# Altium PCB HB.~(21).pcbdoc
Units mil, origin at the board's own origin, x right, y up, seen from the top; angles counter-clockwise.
Board outline 4000 x 2100 mil, 2 copper layers (Top Layer, Bottom Layer); 61 components, 37 nets, 226 pads, 50 vias.
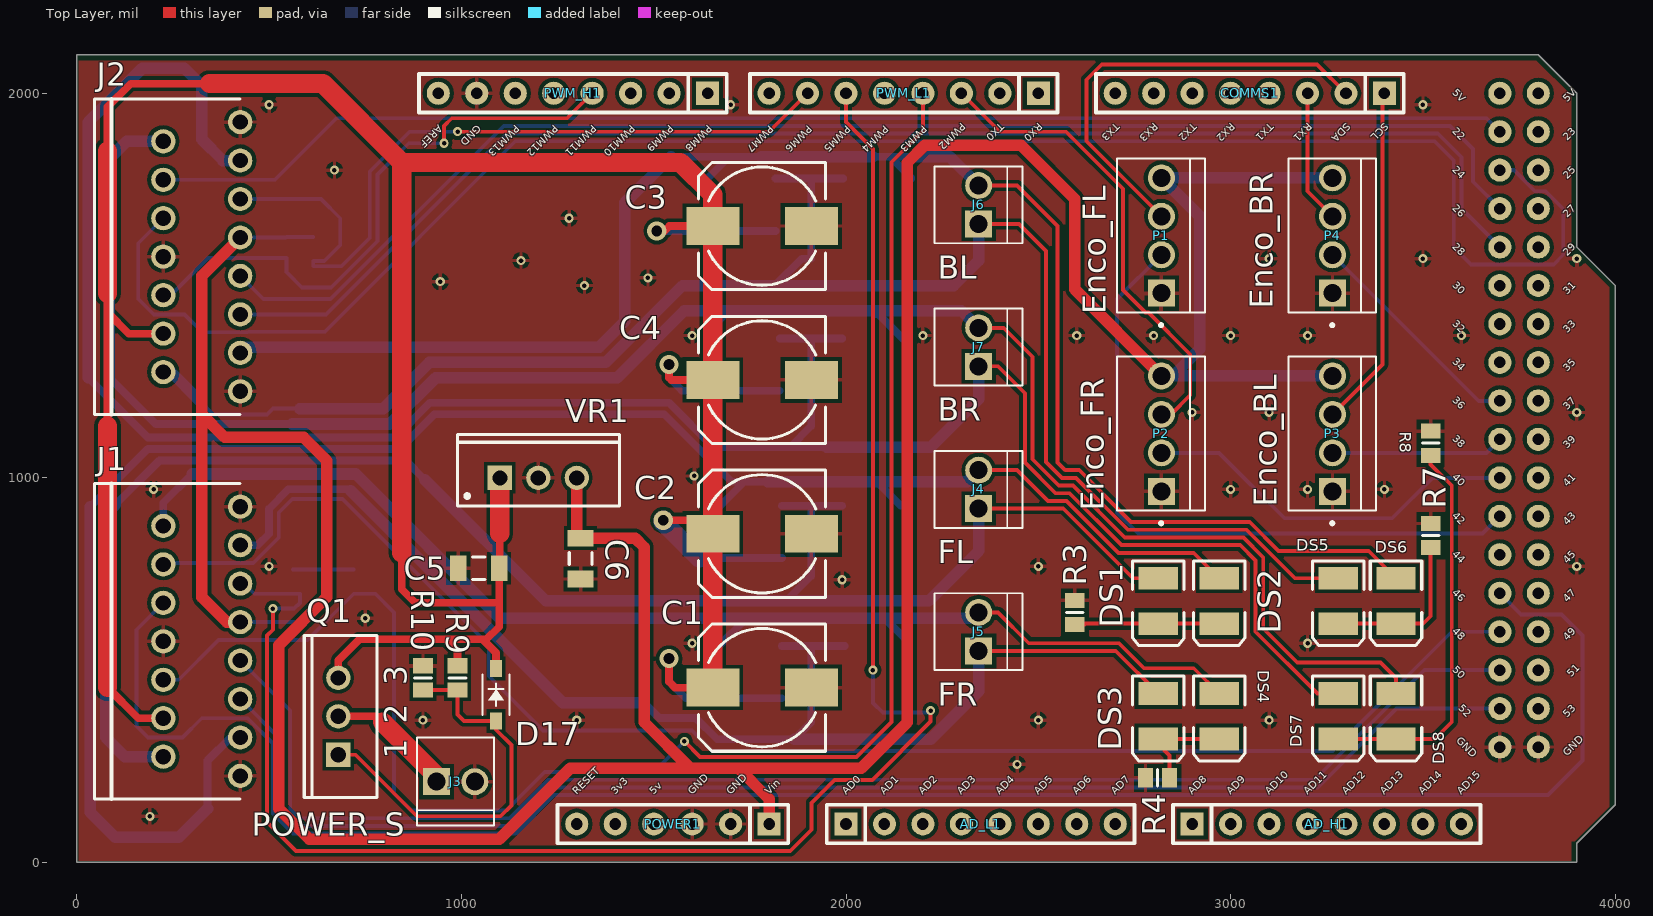
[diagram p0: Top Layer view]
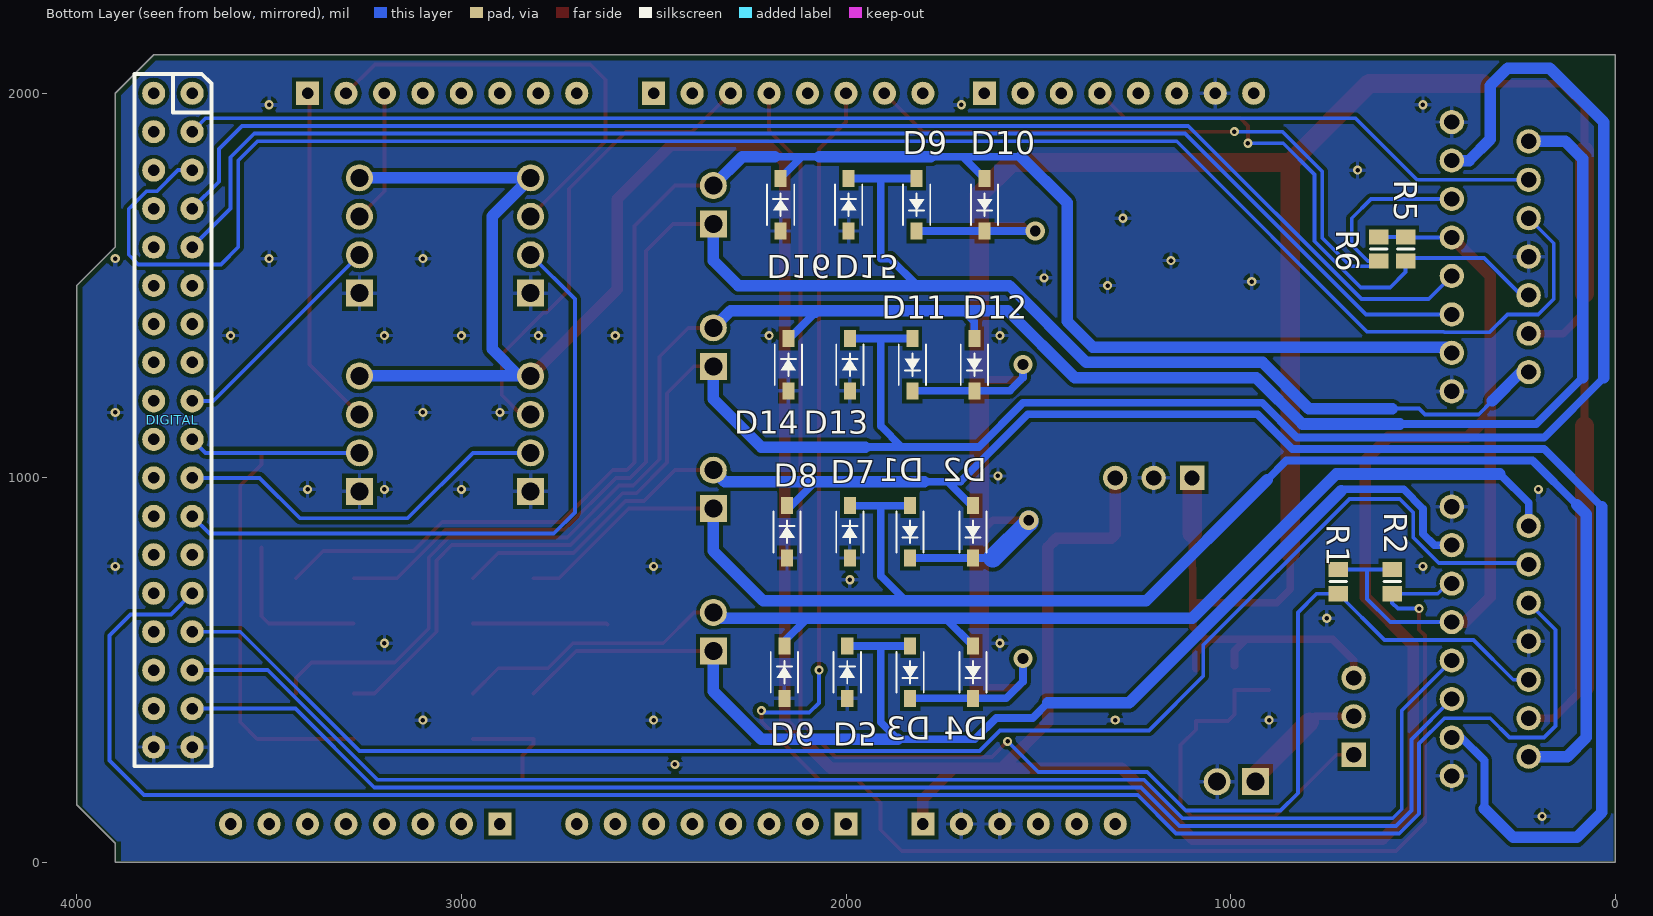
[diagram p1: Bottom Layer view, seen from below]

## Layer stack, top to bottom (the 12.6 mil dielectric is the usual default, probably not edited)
Top Solder: solder mask 0.4, Solder Resist, Dk 3.5
Top Layer: signal copper 1.4
Dielectric1: dielectric 12.6, FR-4, Dk 4.8
Bottom Layer: signal copper 1.4
Bottom Solder: solder mask 0.4, Solder Resist, Dk 3.5

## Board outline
0,0 0,2100 3800,2100 3900,2000 3900,1600 4000,1500 4000,150 3900,50 3900,0

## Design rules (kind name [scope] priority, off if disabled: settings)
Clearance [All] p1: gap=10 ignorepadtopadclearanceinfootprint=FALSE except(0: Arc-Text Track-Text SMDPad-Text THPad-Text Via-Text Fill-Text Poly-Text Region-Text Text-Text)
Clearance POWER [InNet('GND') vs InNet('+12V')] p2: gap=20 ignorepadtopadclearanceinfootprint=FALSE
ComponentClearance [All] p1: gap=7 collisioncheckmode=3 verticalgap=7 showdistances=FALSE
PolygonConnect [All] p1: connectstyle=Relief reliefconductorwidth=10 reliefentries=4 polygonreliefangle="90 Angle" airgapwidth=10
RoutingVias RoutingVias_1 [InNet('+12V')] p1: holewidth=28 width=50 viastyle="Through Hole" minholewidth=28 minwidth=50 maxholewidth=28 maxwidth=50 useviatemplates=TRUE viatemplateguid#1={C0CBB304-7D75-4EF7-981A-080250C0CCCD} viatemplatename#1=v127h71
RoutingVias [All] p2: holewidth=28 width=50 viastyle="Through Hole" minholewidth=28 minwidth=50 maxholewidth=28 maxwidth=50 useviatemplates=TRUE viatemplateguid#1={6204ABBA-D726-4070-AECC-2A288C87648D} viatemplatename#1=v60h30
SilkToSilkClearance [All] p1: silktosilkclearance=5
SilkToSolderMaskClearance SilkscreenOverComponentPads [IsPad] p1: minsilkscreentomaskgap=7 clearancetoexposedcopper=TRUE
SolderMaskExpansion [All] p1: expansion=4
Width motor [InNet('motor_BL1')+InNet('motor_BL2')+InNet('motor_BR1')+InNet('motor_BR2')+InNet('motor_FL1')+InNet('motor_FL2')+InNet('motor_FR1')+InNet('motor_FR2')] p1: maxlimit=30 minlimit=10 preferedwidth=20
Width 12V [InNet('+12V')] p2: maxlimit=50 minlimit=10 preferedwidth=20
Width POWER_route [InNet('VCC')] p3: maxlimit=50 minlimit=15 preferedwidth=20
Width [All] p4: maxlimit=30 minlimit=10 preferedwidth=10
27 further rules are at their usual default settings.

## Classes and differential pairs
component class HB_main: AD_H1 AD_L1 COMMS1 DIGITAL J3 J4 J5 J6 J7 P1 P2 P3 P4 POWER1 PWM_H1 PWM_L1
component class Designator: D9 D10 D11 D12 D13 D14 D15 D16 DS5 DS6 DS7 DS8 J2 R5 R6 R7 R8

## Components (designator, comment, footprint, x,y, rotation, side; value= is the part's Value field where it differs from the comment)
AD_H1 "AD_H" "Header 8x1 8.5mm" 2900,100 r0 top
AD_L1 "AD_L" "Header 8x1 8.5mm" 2000,100 r0 top
C1 "Cap_220u" CAPAE0810X700N 1781.73,454.6 r180 top value=220u
C2 "Cap_220u" CAPAE0810X700N 1781.73,854.6 r180 top value=220u
C3 "Cap_220u" CAPAE0810X700N 1781.73,1654.6 r180 top value=220u
C4 "Cap_220u" CAPAE0810X700N 1781.73,1254.6 r180 top value=220u
C5 "Cap_330n" C1206 1045,765 r180 top value=330n
C6 "Cap_100n" C1206 1310,790 r270 top value=100n
COMMS1 "Communication" "Header 8x1 8.5mm" 3400,2000 r180 top
D1 "Diode Schottky" SOD-123 1833.54,859.53 r90 bottom
D2 "Diode Schottky" SOD-123 1670,859.53 r90 bottom
D3 "Diode Schottky" SOD-123 1833.23,494.76 r90 bottom
D4 "Diode Schottky" SOD-123 1669.69,494.76 r90 bottom
D5 "Diode Schottky" SOD-123 1996.77,494.76 r270 bottom
D6 "Diode Schottky" SOD-123 2160.32,494.76 r270 bottom
D7 "Diode Schottky" SOD-123 1990,859.53 r270 bottom
D8 "Diode Schottky" SOD-123 2153.54,859.53 r270 bottom
D9 "Diode Schottky" SOD-123 1816.46,1710 r90 bottom
D10 "Diode Schottky" SOD-123 1639.68,1710 r90 bottom
D11 "Diode Schottky" SOD-123 1827.48,1294.29 r90 bottom
D12 "Diode Schottky" SOD-123 1666.3,1294.29 r90 bottom
D13 "Diode Schottky" SOD-123 1990,1294.29 r270 bottom
D14 "Diode Schottky" SOD-123 2149.84,1294.29 r270 bottom
D15 "Diode Schottky" SOD-123 1993.23,1710 r270 bottom
D16 "Diode Schottky" SOD-123 2170,1710 r270 bottom
D17 "D Zener" SOD-123 1090,436.1 r270 top
DIGITAL "IO_36" "HEADER 36X 8MM" 3700,2000 r270 bottom
DS1 "LED" 3.5X2.8X1.9 2812.13,680 r270 top
DS2 "LED" 3.5X2.8X1.9 2970,680 r270 top
DS3 "LED" 3.5X2.8X1.9 2812.13,380 r270 top
DS4 "LED" 3.5X2.8X1.9 2970,380 r270 top
DS5 "LED" 3.5X2.8X1.9 3280,680 r270 top
DS6 "LED" 3.5X2.8X1.9 3430,680 r270 top
DS7 "LED" 3.5X2.8X1.9 3280,380 r270 top
DS8 "LED" 3.5X2.8X1.9 3430,380 r270 top
J1 "L298" MultiWatt15 425,65 r90 top
J2 "L298" MultiWatt15 425,1065 r90 top
J3 "POWER_S" Header_2 1085,210.79 r180 top
J4 "FL" Header_2 2344.21,1070 r270 top
J5 "FR" Header_2 2344.21,700 r270 top
J6 "BL" Header_2 2344.21,1810 r270 top
J7 "BR" Header_2 2344.21,1440 r270 top
P1 "Enco_FL" MOLEX_22-27-2081 2819.21,1830 r270 top
P2 "Enco_FR" MOLEX_22-27-2081 2819.21,1315 r270 top
P3 "Enco_BL" MOLEX_22-27-2081 3264.21,1315 r270 top
P4 "Enco_BR" MOLEX_22-27-2081 3264.21,1830 r270 top
POWER1 "POWER" "Header 6x1 8.5mm" 1800,100 r180 top
PWM_H1 "PWM_H" "Header 8x1 8.5mm" 1640,2000 r180 top
PWM_L1 "PWM_L" "Header 8x1 8.5mm" 2500,2000 r180 top
Q1 "MOSFET-P" TO-220-AB 680,380 r90 top
R1 "Res_10k" 6-0805_L 720,730 r270 bottom value=10k
R2 "Res_10k" 6-0805_L 580,730 r90 bottom value=10k
R3 "Res_2.2k" 6-0805_L 2595,650 r270 top value=2.2k
R4 "Res_2.2k" 6-0805_L 2810,220 r0 top value=2.2k
R5 "Res_10k" 6-0805_L 545,1595 r270 bottom value=10k
R6 "Res_10k" 6-0805_L 615,1595 r90 bottom value=10k
R7 "Res_2.2k" 6-0805_L 3520,850 r270 top value=2.2k
R8 "Res_2.2k" 6-0805_L 3520,1090 r270 top value=2.2k
R9 "Res_100k" 6-0805_L 990,480 r90 top value=100k
R10 "Res_1k" 6-0805_L 900,480 r270 top value=1k
VR1 "7805" TO-220AB 1200,1000 r0 top

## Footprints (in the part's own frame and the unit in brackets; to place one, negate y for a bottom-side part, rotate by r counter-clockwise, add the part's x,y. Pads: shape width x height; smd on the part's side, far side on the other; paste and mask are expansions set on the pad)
3.5X2.8X1.9 [mm] "SM LED; 2 C-Bend Leads; Body 3.5 x 2.8 x 1.9 mm, inc leads (LxWxH typ)"
  rect 1.5x2.6 smd: 1(-1.5,0) 2(1.5,0)
  silkscreen extent -2.65,-1.7 2.95,1.7
6-0805_L [mm] "Chip Resistor, Body 2.0x1.2mm, IPC High Density"
  rect 1x1.3 smd: 1(-0.8,0) 2(0.8,0)
  silkscreen extent 0,-0.55 0,0.55, body extent -1.07,-0.7 1.07,0.7, height 0.7
C1206 [mm] "Chip Capacitor, Body 3.2x1.6mm, IPC High Density"
  rect 1.1x1.7 smd: 1(-1.35,0) 2(1.35,0)
  silkscreen extent -0.4,-0.75 0.4,0.75, body extent -1.7,-0.9 1.7,0.9, height 1.3
CAPAE0810X700N [mm]
  rect 3.5x2.5 smd: NEG(-3.25,0) POS(3.25,0)
  silkscreen extent -4.2,-4.2 4.2,4.2
"Header 6x1 8.5mm" [mil] "Stackable 6 pin header"
  rect 60x60 hole 30: 1(0,0)
  round 60 hole 30: 2(100,0) 3(200,0) 4(300,0) 5(400,0) 6(500,0)
  silkscreen extent -50,-50 550,50, body extent -50,-50 550,50, height 335
"Header 8x1 8.5mm" [mil] "Stackable 8 pin header"
  rect 60x60 hole 30: 1(0,0)
  round 60 hole 30: 2(100,0) 3(200,0) 4(300,0) 5(400,0) 6(500,0) 7(600,0) 8(700,0)
  silkscreen extent -50,-50 750,50, body extent -50,-50 750,50, height 335
"HEADER 36X 8MM" [mil] "Stackable 10 pin header"
  round 60 hole 30: 1(0,0) 2(0,-100) 3(100,0) 4(100,-100) 5(200,0) 6(200,-100) 7(300,0) 8(300,-100) 9(400,0) 10(400,-100) 11(500,0) 12(500,-100) 13(600,0) 14(600,-100) 15(700,0) 16(700,-100) 17(800,0) 18(800,-100) 19(900,0) 20(900,-100) 21(1000,0) 22(1000,-100) 23(1100,0) 24(1100,-100) 25(1200,0) 26(1200,-100) 27(1300,0) 28(1300,-100) 29(1400,0) 30(1400,-100) 31(1500,0) 32(1500,-100) 33(1600,0) 34(1600,-100) 35(1700,0) 36(1700,-100)
  silkscreen extent -50,-150 1750,50, body extent -50,-150 1750,50, height 335
Header_2 [mm]
  rect 1.785x1.785 hole 1.19: 1(3.81,0.02)
  round 1.785 hole 1.19: 2(1.27,0.02)
  silkscreen extent 0,-2.9 5.08,2.9
MOLEX_22-27-2081 [mm]
  rect 1.785x1.785 hole 1.19: 1(8.89,0.02)
  round 1.785 hole 1.19: 2(6.35,0.02) 3(3.81,0.02) 4(1.27,0.02)
  silkscreen extent 0,-2.9 11.1,2.9
MultiWatt15 [mm] "MultiWatt15; 15 Leads; Row Spacing 5.08 mm; Pitch 2.54 mm"
  round 1.6 hole 1: CSA(4.064,0) CSB(21.844,0) ENA(10.414,5.08) ENB(16.764,0) GND(12.954,5.08) input1(9.144,0) input2(11.684,0) input3(15.494,5.08) input4(18.034,5.08) OUT1(5.334,5.08) OUT2(6.604,0) OUT3(19.304,0) OUT4(20.574,5.08) VS(7.874,5.08) VSS(14.224,0)
  silkscreen extent 2.54,0 23.37,9.63
SOD-123 [mm]
  rect 1.12x0.8 smd: 1(-1.73,0) 2(1.73,0)
  silkscreen extent -1.35,-0.9 1.35,0.9
TO-220-AB [mm] "TO, Thru-Hole, Vertical, Heatsink Mounted; 3 In-Line Leads; Pitch 2.54 mm"
  round 1.6 hole 1: D(0,0) S(2.54,0)
  rect 1.6x1.6 hole 1: G(-2.54,0)
  silkscreen extent -5.35,-2.55 5.35,2.25
TO-220AB [mm] "TO, Thru-Hole, Vertical, Heatsink Mounted; 3 In-Line Leads; Pitch 2.54 mm"
  rect 1.6x1.6 hole 1: 1(-2.54,0)
  round 1.6 hole 1: 2(0,0) 3(2.54,0)
  silkscreen extent -5.35,-1.85 5.35,2.85, body extent -5.4,-1.9 5.4,2.9, height 19.3

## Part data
AD_H1 AD_L1 COMMS1 PWM_H1 PWM_L1: "Header, 8-Pin"
C1 C2 C3 C4: "Condensateur polatisé"
C5 C6: "Condensateur"
D17: "Zener Diode"
DIGITAL: "Header, 36-Pin"
DS1 DS2 DS3 DS4 DS5 DS6 DS7 DS8: Color=Rouge
J1 J2: "Connecteur"
J3 J4 J5 J6 J7: library part "Connecteur 2", "Connecteur"
P1 P2 P3 P4: library part "Header 4", "Header, 4-Pin"
POWER1: "Header, 6-Pin"
Q1: "P-Channel MOSFET"
R1 R2 R3 R4 R5 R6 R7 R8 R9 R10: "Résistance standard"
VR1: "Régulateur 5V"

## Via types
v1: diameter 23.62, hole 11.81, Top Layer to Bottom Layer, 46 vias
v2: diameter 50, hole 28, Top Layer to Bottom Layer, 4 vias

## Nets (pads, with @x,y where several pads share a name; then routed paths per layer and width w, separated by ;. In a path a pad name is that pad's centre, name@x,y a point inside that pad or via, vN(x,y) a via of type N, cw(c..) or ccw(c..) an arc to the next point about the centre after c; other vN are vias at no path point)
+5V: C6.1 J1.VSS J2.VSS P1.4 P2.4 P3.4 P4.4 POWER1.1 R1.1 R2.2 R5.1 R6.2 VR1.3 | length 10043.4
  Top Layer w30: J1.VSS 390,625 325,690 325,1165 ; J2.VSS 325,1525 325,1165 ; VR1.3 1300,853.15 C6.1 1451.85,843.15 1475,820 1475,365 1595.35,244.65 ; POWER1.1 1800,165 1720.35,244.65 ; P2.4 2595,1490 2595,1725 2455,1865 2205,1865 2159.68,1819.68 2159.68,1750 2159.68,364.68 2039.65,244.65 1720.35,244.65 ; 325,1165 385,1105 590,1105 650,1045 650,690 525,565 525,140 605,60 1098.28,60 1282.93,244.65 1595.35,244.65 ; 1595.35,244.65 1720.35,244.65
  Bottom Layer w10: J1.VSS 585,625 645,685 645,761.5 ; J2.VSS 543.5,1625 R5.1 R6.2 ; R2.2@561.5,761.5 R2.2 645,761.5 ; R1.1 645,761.5 ; P2.4 P2.4@2820,1275
  Bottom Layer w30: P2.4 P2.4@2850,1265 ; P3.4 P2.4@2850,1265 ; P4.4 P1.4 2920,1680 2920,1335 P2.4@2850,1265
+12V: C1.POS C2.POS C3.POS C4.POS C5.1 D1.1 D2.1 D3.1 D4.1 D9.1 D10.1 D11.1 D12.1 D17.1 J1.VS J2.VS Q1.S R9.2 VR1.1 | length 9286
  Top Layer w20: 80,455 160,375 J1.VS ; 80,1135 80,1430 ; 80,1480 80,1430 ; 80,1850 80,1965 140,2025 345,2025 ; J2.VS 135,1375 80,1430 ; Q1.S 680,525 735,580 960,580 ; 845,805 845,710 880,675 1098.15,675 ; R9.2 990,550 960,580 ; D17.1 1090,545 1055,580 ; 1100,855 1100,766.85 C5.1 1098.15,675 ; v2(1508.11,1641.89) 1527.68,1641.89 1540.4,1654.6 C3.POS ; v2(1525,890) 1618.38,890 C2.POS ; v2(1540,530) 1540,470 1555.4,454.6 C1.POS ; v2(1540,1295) 1540,1260 1545.4,1254.6 C4.POS ; 960,580 1055,580 ; 1055,580 1065,580 1098.15,613.15 1098.15,675
  Top Layer w50: 80,455 80,1135 ; 80,1480 80,1850 ; 345,2025 640,2025 845,1820 ; 845,805 845,1820 ; 1100,855 VR1.1 ; C1.POS C2.POS C4.POS C3.POS 1653.78,1736.22 1570,1820 845,1820
  Bottom Layer w20: v2(1508.11,1641.89) D10.1 D9.1 ; v2(1540,530) 1540,470 1583.35,426.65 D4.1 D3.1 ; v2(1540,1295) 1540,1260 1573.82,1226.18 D12.1 D11.1 ; 1618.19,791.42 D2.1 D1.1
  Bottom Layer w50: v2(1525,890) 1525,884.6 1618.19,791.42
Com1_1: DIGITAL.33 J1.input1 | length 3646.4
  Bottom Layer w10: J1.input1 530,320 530,135 570,95 1133.28,95 1233.28,195 3226.57,195 3431.57,400 DIGITAL.33
Com1_2: DIGITAL.31 J1.input2 | length 3754.7
  Bottom Layer w10: J1.input2 555,395 555,138.28 578.28,115 1125,115 1225,215 3218.28,215 3503.28,500 DIGITAL.31
Com1_E: J1.ENA PWM_L1.4 R1.2 | length 4291.7
  Top Layer w10: v1(1580,315) 1620.35,274.65 2027.22,274.65 2118.11,365.54 2118.11,1820.54 2200,1902.43 PWM_L1.4
  Bottom Layer w10: J1.ENA 265,475 368.5,578.5 600,578.5 R1.2 776.5,698.5 825,650 825,180 870,135 1116.72,135 1216.72,235 1500,235 v1(1580,315)
Com2_1: DIGITAL.27 J1.input3 | length 5037.6
  Bottom Layer w10: J1.input3 155,605 155,355 185,325 275,325 325,375 444.26,375 510,309.26 510,126.72 561.72,75 1141.57,75 1241.57,175 3825,175 3915,265 3915,590 3860,645 3755,645 DIGITAL.27
Com2_2: DIGITAL.29 J1.input4 | length 4032.3
  Bottom Layer w10: J1.input4 225,778.5 458.86,778.5 525,844.64 525,909.64 560.36,945 691.01,945 1071.01,565 1071.01,484.62 1212.44,343.19 1599.38,343.19 1652.57,290 3265,290 3575,600 DIGITAL.29
Com2_E: J1.ENB PWM_L1.6 R2.1 | length 4568.8
  Top Layer w10: v1(510,660) 510,605 495,590 495,105 570,30 1855,30 1910,85 1910,155 1969.65,214.65 2068.44,214.65 2220,366.2 v1(2220,395) ; PWM_L1.6 2000,1925 2070,1855 v1(2070,500)
  Bottom Layer w10: J1.ENB 435,725 461.5,698.5 R2.1 580,675 565,660 v1(510,660) ; v1(2070,500) 2070,415 2095.39,389.61 2214.61,389.61 v1(2220,395)
Com3_1: DIGITAL.9 J2.input1 | length 3670
  Bottom Layer w10: J2.input1 648.28,1425 1118.28,1895 3538.43,1895 3600,1833.43 3600,1700 DIGITAL.9
Com3_2: DIGITAL.7 J2.input2 | length 3625.1
  Bottom Layer w10: J2.input2 485,1465 660,1465 1110,1915 3570,1915 3630,1855 3630,1770 DIGITAL.7
Com3_E: J2.ENA PWM_H1.4 R5.2 | length 1545.2
  Top Layer w10: v1(955,1870) 955,1915 975,1935 1275,1935 PWM_H1.4
  Bottom Layer w10: J2.ENA 245,1475 341.5,1571.5 545,1571.5 R5.2 545,1535 585,1495 661.72,1495 781.72,1615 781.72,1788.43 863.28,1870 v1(955,1870)
Com4_1: DIGITAL.5 J2.input3 | length 4783.8
  Bottom Layer w10: J2.input3 160,1610 160,1465 200,1425 280,1425 326.5,1378.5 444.26,1378.5 445.76,1380 645,1380 1140,1875 3530.15,1875 3580,1825.15 3580,1600 3625,1555 3840,1555 3865,1580 3865,1698.64 3818.64,1745 3791.36,1745 3736.36,1800 DIGITAL.5
Com4_2: DIGITAL.3 J2.input4 | length 3555.8
  Bottom Layer w10: J2.input4 515,1775 675,1935 3665,1935 DIGITAL.3
Com4_E: J2.ENB PWM_L1.7 R6.1 | length 2024.4
  Top Layer w10: v1(990,1900) 1800,1900 PWM_L1.7
  Bottom Layer w10: J2.ENB 635,1725 685,1675 685,1605 643.5,1563.5 R6.1 615,1550 688.43,1550 761.72,1623.28 761.72,1796.72 865,1900 v1(990,1900)
Enco_GPIO1: DIGITAL.23 P1.2 | length 1754.1
  Bottom Layer w10: P1.2 2705,1465 2705,910 2760,855 3655,855 DIGITAL.23
Enco_GPIO2: DIGITAL.21 P2.2 | length 993.9
  Bottom Layer w10: P2.2 2970,1065 3140,895 3420,895 3525,1000 DIGITAL.21
Enco_GPIO3: DIGITAL.19 P3.2 | length 449.5
  Bottom Layer w10: P3.2 3665,1065 DIGITAL.19
Enco_GPIO4: DIGITAL.17 P4.2 | length 617.4
  Top Layer w10: DIGITAL.17@3675,1200 DIGITAL.17
  Bottom Layer w10: P4.2 3645,1200 DIGITAL.17
Enco_Int1: COMMS1.2 P1.3 | length 1158.4
  Top Layer w10: P1.3 2625,1875 2625,2035 2665,2075 3225,2075 COMMS1.2
Enco_Int2: P2.3 PWM_L1.3 | length 1232.2
  Top Layer w10: PWM_L1.3 2400,1900 2571.72,1900 2720,1751.72 2720,1488.51 2778.65,1429.86 2786.28,1429.86 2895,1321.14 2895,1215 2845,1165 P2.3
Enco_Int3: COMMS1.1 P3.3 | length 890.9
  Top Layer w10: P3.3 3395,1295 3395,1995 COMMS1.1
Enco_Int4: COMMS1.3 P4.3 | length 346.9
  Top Layer w10: COMMS1.3 3200,1745 P4.3
GND: C1.NEG C2.NEG C3.NEG C4.NEG C5.2 C6.2 D5.2 D6.2 D7.2 D8.2 D13.2 D14.2 D15.2 D16.2 DIGITAL.35 DIGITAL.36 J1.CSA J1.CSB J1.GND J2.CSA J2.CSB J2.GND J3.2 P1.1 P2.1 P3.1 P4.1 POWER1.2 POWER1.3 PWM_H1.7 R3.1 R4.1 R7.1 R8.1 R10.1 VR1.2
  other v1: 190,120 2445,255 900,370 1300,370 2500,370 3100,370 1600,570 3200,570 750,635 1990,735 500,770 2500,770 3900,770 200,970 3000,970 3200,970 3400,970 1605,1005 2900,1170 3100,1170 3900,1170 1600,1370 2200,1370 2600,1370 2800,1370 3000,1370 3200,1370 3600,1370 1320,1500 945,1510 1485,1520 1155,1565 3100,1570 3500,1570 3900,1570 1280,1675 670,1800 500,1970 1700,1970 3500,1970
motor_BL1: D9.2 D15.1 DS5.1 J2.OUT1 J6.1 | length 4572.9
  Top Layer w10: J6.1 2450,1660 2520,1590 2520,1041.57 2561.57,1000 2598.14,1000 2733.14,865 3041.57,865 3167.51,739.06 DS5.1
  Bottom Layer w10: 320,1200 355,1165 495,1165 510,1180 580,1180
  Bottom Layer w20: 1815,1500 1885,1570 1910,1570 1910,1778.11 ; D9.2 1910,1778.11 ; D15.1 1910,1778.11
  Bottom Layer w30: J2.OUT1 245,1275 320,1200 ; 580,1180 796.51,1180 916.51,1300 1375,1300 1575,1500 1815,1500 2280,1500 2345,1565 J6.1
motor_BL2: D10.2 D16.1 DS6.1 J2.OUT2 J6.2 | length 4371.3
  Top Layer w10: J6.2 2445,1760 2550,1655 2550,1039.85 2569.85,1020 2606.42,1020 2741.42,885 3049.85,885 3124.85,810 3359.06,810 DS6.1
  Bottom Layer w20: 1545,1835 1696.57,1835 ; D10.2 1696.57,1835 ; 1780,1835 1696.57,1835 ; 2070,1835 2115,1835 ; D16.1 2170,1780 2115,1835 ; 2185,1835 2115,1835
  Bottom Layer w30: J2.OUT2 440,1340 1358.43,1340 1425,1406.57 1425,1715 1545,1835 ; 1780,1835 2070,1835 ; 2185,1835 2270,1835 J6.2
motor_BR1: D11.2 D13.1 DS7.1 J2.OUT3 J7.1 | length 5869.3
  Top Layer w10: J7.1 2395,1290 2465,1220 2465,1040 2545,960 2581.57,960 2716.57,825 3025,825 3065,785 3065,600 3225.94,439.06 DS7.1
  Bottom Layer w20: 30,1260 185,1105 827.57,1105 917.57,1195 1539.85,1195 1654.85,1080 1855,1080 ; D11.2 1910,1362.4 ; 1950,1080 1855,1080 ; D13.1 1910,1362.4 ; 1855,1080 1910,1135 1910,1362.4
  Bottom Layer w30: 30,1260 30,1925 170,2065 280,2065 325,2020 325,1880 380,1825 J2.OUT3 ; 1950,1080 2220,1080 2345,1205 J7.1
motor_BR2: D12.2 D14.1 DS8.1 J2.OUT4 J7.2 | length 5136.1
  Top Layer w10: J7.2 2410,1390 2485,1315 2485,1048.28 2553.28,980 2589.85,980 2724.85,845 3033.28,845 3085,793.28 3085,608.28 3173.28,520 3390,520 3430,480 DS8.1
  Bottom Layer w20: 85,1260 205,1140 560,1140 ; D12.2 1666.3,1406.3 1695,1435 ; 2080,1430 2147.6,1362.4 D14.1
  Bottom Layer w30: 85,1260 85,1830 130,1875 J2.OUT4 ; 560,1140 813.08,1140 933.08,1260 1405,1260 1580,1435 1695,1435 2075,1435 ; 2080,1430 2075,1435 ; J7.2 2300,1435 2075,1435
motor_FL1: D1.2 D7.1 DS1.1 J1.OUT1 J4.1 | length 4366.8
  Top Layer w10: J4.1 2565,920 2745.94,739.06 DS1.1
  Bottom Layer w20: 100,930 215,1045 855,1045 905,995 ; D1.2 1910,927.64 ; 1845,680 1910,745 1910,927.64 ; D7.1 1910,927.64
  Bottom Layer w30: 100,930 75,905 75,325 125,275 J1.OUT1 ; 905,995 1220,680 1845,680 2215,680 2345,810 J4.1
motor_FL2: D2.2 D8.1 DS2.1 J1.OUT2 J4.2 | length 4818.7
  Top Layer w10: J4.2 2445,1020 2525,940 2573.28,940 2708.28,805 2904.06,805 DS2.1
  Bottom Layer w20: 35,925 185,1075 840,1075 930,1165 1527.43,1165 1702.43,990 1735,990 ; 340,140 340,265 400,325 J1.OUT2 ; D2.2 1672.64,927.64 1735,990 ; 1797.02,990 1735,990 ; 2080,990 2142.36,927.64 D8.1
  Bottom Layer w30: 35,925 35,130 100,65 265,65 340,140 ; 1797.02,990 2080,990 2315,990 J4.2
motor_FR1: D3.2 D5.1 DS3.1 J1.OUT3 J5.1 | length 3394.4
  Top Layer w10: J5.1 2701.18,550 DS3.1
  Bottom Layer w20: J1.OUT3@425,835 J1.OUT3 470,825 500,855 500,920 550,970 715.5,970 ; 1475,415 1514.44,375.56 1609.44,375.56 1665,320 1865,320 1910,365 1910,562.87 ; D3.2 1910,562.87 ; D5.1 1910,562.87
  Bottom Layer w30: 711.97,966.46 1263.43,415 1475,415 ; 1865,320 2220,320 2345,445 J5.1
motor_FR2: D4.2 D6.1 DS4.1 J1.OUT4 J5.2 | length 3284.1
  Top Layer w10: J5.2 2395,650 2475,570 2710,570 2775,505 2904.06,505 DS4.1
  Bottom Layer w20: J1.OUT4 225,935 300,1010 ; D4.2 1741.81,635 ; 2100,635 2160.32,574.68 D6.1
  Bottom Layer w30: 300,1010 725,1010 1100,635 1741.81,635 2100,635 2330,635 J5.2
NetD17_2: D17.2 Q1.G R9.1 R10.2 | length 1024.8
  Top Layer w10: Q1.G 725,280 885,120 1101.72,120 1130,148.28 1130,305 1090,345 D17.2 1007.01,367.99 990,385 R9.1 R10.2
NetDS1_2: DS1.2 DS2.2 R3.2 | length 351
  Top Layer w10: R3.2@2620,618.5 2622.44,620.94 DS1.2 DS2.2
NetDS3_2: DS3.2 DS4.2 R4.2 | length 271
  Top Layer w10: R4.2 2841.5,278.5 2812.13,307.87 DS3.2 DS4.2
NetDS5_2: DS5.2 DS6.2 R7.2 | length 426.4
  Top Layer w10: DS5.2 DS6.2 3500.94,620.94 3520,640 R7.2
NetDS7_2: DS7.2 DS8.2 R8.2 | length 1029.5
  Top Layer w10: DS7.2 DS8.2 3530.94,320.94 3575,365 3575,980 3520,1035 R8.2
VCC: J3.1 Q1.D | length 334.2
  Top Layer w20: Q1.D 780,380 795,365
  Top Layer w50: 795,365 935,225 J3.1
pads on no net: AD_H1.1 AD_H1.2 AD_H1.3 AD_H1.4 AD_H1.5 AD_H1.6 AD_H1.7 AD_H1.8 AD_L1.1 AD_L1.2 AD_L1.3 AD_L1.4 AD_L1.5 AD_L1.6 AD_L1.7 AD_L1.8 COMMS1.4 COMMS1.5 COMMS1.6 COMMS1.7 COMMS1.8 DIGITAL.1 DIGITAL.2 DIGITAL.4 DIGITAL.6 DIGITAL.8 DIGITAL.10 DIGITAL.11 DIGITAL.12 DIGITAL.13 DIGITAL.14 DIGITAL.15 DIGITAL.16 DIGITAL.18 DIGITAL.20 DIGITAL.22 DIGITAL.24 DIGITAL.25 DIGITAL.26 DIGITAL.28 DIGITAL.30 DIGITAL.32 DIGITAL.34 POWER1.4 POWER1.5 POWER1.6 PWM_H1.1 PWM_H1.2 PWM_H1.3 PWM_H1.5 PWM_H1.6 PWM_H1.8 PWM_L1.1 PWM_L1.2 PWM_L1.5 PWM_L1.8

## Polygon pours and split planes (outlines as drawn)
GND on Bottom Layer "Bottom Layer-GND " (solid, remove dead copper, pour order 6): 5,5 5,2085 3795,2085 3885,1995 3885,1595 3985,1495 3985,145 3895,55 3885,55 3885,5
GND on Bottom Layer "GND_L02_P002" (solid, remove dead copper, pour order 2): 1360,2210
GND on Top Layer "Top Layer-GND" (solid, remove dead copper, pour order 4): 5,2085 5,5 3885,5 3885,55 3895,55 3985,145 3985,1495 3880,1600 3885,1605 3885,1995 3795,2085

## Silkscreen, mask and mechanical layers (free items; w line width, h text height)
Top Overlay:
  text "5V" at 3575,2000 h20 r315
  text "5V" at 3875,1975 h20 r45
  text "PWM2" at 2300,1925 h20 r225
  text "TX0" at 2400,1925 h20 r225
  text "RX0" at 2500,1925 h20 r225
  text "TX3" at 2700,1925 h20 r225
  text "RX3" at 2800,1925 h20 r225
  text "TX2" at 2900,1925 h20 r225
  text "RX2" at 3000,1925 h20 r225
  text "TX1" at 3100,1925 h20 r225
  text "RX1" at 3200,1925 h20 r225
  text "SDA" at 3300,1925 h20 r225
  text "SCL" at 3400,1925 h20 r225
  text "AREF" at 940,1920 h20 r225
  text "GND" at 1040,1920 h20 r225
  text "PWM13" at 1140,1920 h20 r225
  text "PWM12" at 1240,1920 h20 r225
  text "PWM11" at 1340,1920 h20 r225
  text "PWM10" at 1440,1920 h20 r225
  text "PWM9" at 1540,1920 h20 r225
  text "PWM8" at 1640,1920 h20 r225
  text "PWM7" at 1800,1917.93 h20 r225
  text "PWM6" at 1900,1917.93 h20 r225
  text "PWM5" at 2000,1917.93 h20 r225
  text "PWM4" at 2100,1917.93 h20 r225
  text "PWM3" at 2200,1917.93 h20 r225
  text "22" at 3575,1900 h20 r315
  text "23" at 3875,1875 h20 r45
  text "24" at 3575,1800 h20 r315
  text "25" at 3875,1775 h20 r45
  text "26" at 3575,1700 h20 r315
  text "27" at 3875,1675 h20 r45
  text "28" at 3575,1600 h20 r315
  text "29" at 3875,1575 h20 r45
  text "30" at 3575,1500 h20 r315
  text "31" at 3875,1475 h20 r45
  text "32" at 3575,1400 h20 r315
  text "33" at 3875,1375 h20 r45
  text "34" at 3575,1300 h20 r315
  text "35" at 3875,1275 h20 r45
  text "36" at 3575,1200 h20 r315
  text "37" at 3875,1175 h20 r45
  text "38" at 3575,1100 h20 r315
  text "39" at 3875,1075 h20 r45
  text "40" at 3575,1000 h20 r315
  text "41" at 3875,975 h20 r45
  text "42" at 3575,900 h20 r315
  text "43" at 3875,875 h20 r45
  text "44" at 3575,800 h20 r315
  text "45" at 3875,775 h20 r45
  text "46" at 3575,700 h20 r315
  text "47" at 3875,675 h20 r45
  text "48" at 3575,600 h20 r315
  text "49" at 3875,575 h20 r45
  text "50" at 3575,500 h20 r315
  text "51" at 3885,480 h20 r45
  text "52" at 3590,400 h20 r315
  text "53" at 3875,375 h20 r45
  text "GND" at 3585,315 h20 r315
  text "GND" at 3875,275 h20 r45
  text "RESET" at 1300,175 h20 r45
  text "3v3" at 1400,175 h20 r45
  text "5v" at 1500,175 h20 r45
  text "GND" at 1600,175 h20 r45
  text "GND" at 1700,175 h20 r45
  text "Vin" at 1800,175 h20 r45
  text "AD0" at 2000,175 h20 r45
  text "AD1" at 2100,175 h20 r45
  text "AD2" at 2200,175 h20 r45
  text "AD3" at 2300,175 h20 r45
  text "AD4" at 2400,175 h20 r45
  text "AD5" at 2500,175 h20 r45
  text "AD6" at 2600,175 h20 r45
  text "AD7" at 2700,175 h20 r45
  text "AD8" at 2900,175 h20 r45
  text "AD9" at 3000,175 h20 r45
  text "AD10" at 3100,175 h20 r45
  text "AD11" at 3200,175 h20 r45
  text "AD12" at 3300,175 h20 r45
  text "AD13" at 3400,175 h20 r45
  text "AD14" at 3500,175 h20 r45
  text "AD15" at 3600,175 h20 r45
Mechanical 1:
  the board outline again, w5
